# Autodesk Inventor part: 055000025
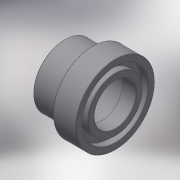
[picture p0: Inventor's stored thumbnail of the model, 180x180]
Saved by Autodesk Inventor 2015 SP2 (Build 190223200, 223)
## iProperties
Created: 2017-10
Part Number: 055000025
Material: Generic
Description: PLASSON FLANGE AD.+O-RING-CE 25
Document SubType Name: Modeling
Designer: KIM
Density: 1 g/cm^3
Appearance: Default
Author: KIM
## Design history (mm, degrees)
derived "055000.ipt"
feature "Solid1::055000.ipt"
tag "TaggingFeature1"
body "Solid1"
other parameters: "d0" = 25, "d1" = 33, "d2" = 25, "d3" = 22.5, "d5" = 19, "d6" = 41, "d8" = 3, "d11" = 0.25, "d12" = 3, "d15" = 2.775, "d_" = 25, "E_" = 33, "E_1" = 41, "l_" = 19, "H_" = 25, "d14" = 9.25
